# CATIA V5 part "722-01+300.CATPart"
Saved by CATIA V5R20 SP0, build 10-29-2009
Part number: 722-01+300
Revision: TUTTO
Definition: NON CONOSCIUTO
Nomenclature: 722-01+300
Source: Unknown
Bounding box of the stored display mesh (mm): x -45.5 to 45.5, y -20 to 20, z -5 to 300
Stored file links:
  C:\Users\Utente\Desktop\IO LAVORO\3D X SITO CF\ULTIMI CATALOGO VERDE\3D files 722\722-01+300.CATPart
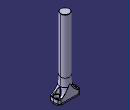
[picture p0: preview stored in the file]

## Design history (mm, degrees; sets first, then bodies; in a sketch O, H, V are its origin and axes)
Body1 "Smusso2" (main body)
  Solid1: solid without history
